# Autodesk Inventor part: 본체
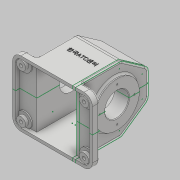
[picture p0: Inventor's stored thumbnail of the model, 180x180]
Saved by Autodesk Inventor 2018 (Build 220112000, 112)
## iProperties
Created: 2022-12
Part Number: 본체
Material: 일반
Document SubType Name: Modeling
Designer: home
Density: 1 g/cm^3
Appearance: 기본값
Author: home
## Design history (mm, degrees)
sketch "스케치1"
  geometry: L1 (53, -55)-(-53, -55); L2 (-67, -41)-(-67, 41); L3 (-53, 55)-(53, 55); L4 (67, 41)-(67, -41); L5 (67, -55)-(-67, 55); L6 (-67, -55)-(67, 55); A1 r 14 centre (53, -41) between (53, -55) and (67, -41); A2 r 14 centre (-53, -41) between (-67, -41) and (-53, -55); A3 r 14 centre (-53, 41) between (-53, 55) and (-67, 41); A4 r 14 centre (53, 41) between (67, 41) and (53, 55); 1 further point
  constraints: 12 end point, 8 point on circle, 8 point on line, 8 tangent, 4 centre point, 3 equal radius, 2 midpoint, 2 parallel, 1 horizontal, 1 perpendicular
  dimensions: "d0" = 134 distance of L5.end L6.end; "d1" = 110 distance of L6.start L5.end; "d2" = 14 radius of A1
extrude "돌출1" new body sketch "스케치1" distance "d3" = 12; taper "d4" = 0 deg
sketch "스케치2"
  geometry: L1 (67, 41)-(67, -41) reference; L2 (53, -55)-(-53, -55) reference; L3 (-67, -41)-(-67, 41) reference; L4 (-53, 55)-(53, 55) reference; C1 r 7.5 at (-53, 41); C2 r 7.5 at (53, 41); C3 r 7.5 at (-53, -41); C4 r 7.5 at (53, -41); A1 r 14 centre (53, 41) between (67, 41) and (53, 55) reference; A2 r 14 centre (53, -41) between (53, -55) and (67, -41) reference; A3 r 14 centre (-53, -41) between (-67, -41) and (-53, -55) reference; A4 r 14 centre (-53, 41) between (-53, 55) and (-67, 41) reference; 1 further point
  constraints: 4 centre point, 4 coincident
  dimensions: "d5" = 15 diameter of C1; "d6" = 15 diameter of C2; "d7" = 15 diameter of C3; "d8" = 15 diameter of C4
extrude "돌출2" cut sketch "스케치2" distance "d9" = 2; taper "d10" = 0 deg
sketch "스케치3"
  geometry: L1 (120, 0)-(120, -82) reference; L2 (106, -96)-(0, -96) reference; L3 (-14, -82)-(-14, 0) reference; L4 (0, 14)-(106, 14) reference; C1 r 7.5 at (0, -82) reference; C2 r 7.5 at (0, 0) reference; C3 r 7.5 at (106, 0) reference; C4 r 7.5 at (106, -82) reference; C5 r 2.75 at (0, 0); C6 r 2.75 at (106, 0); C7 r 2.75 at (0, -82); C8 r 2.75 at (106, -82); A1 r 14 centre (106, 0) between (120, 0) and (106, 14) reference; A2 r 14 centre (106, -82) between (106, -96) and (120, -82) reference; A3 r 14 centre (0, -82) between (-14, -82) and (0, -96) reference; A4 r 14 centre (0, 0) between (0, 14) and (-14, 0) reference; 1 further point
  constraints: 4 centre point, 4 coincident
  dimensions: "d11" = 5.5 diameter of C5; "d12" = 5.5 diameter of C6; "d13" = 5.5 diameter of C7; "d14" = 5.5 diameter of C8
extrude "돌출3" cut sketch "스케치3" extent not by distance; stored distance "d15" = 2; taper "d16" = 0 deg
sketch "스케치4"
  geometry: L1 (12, -55)-(0, -55) reference; L2 (0, -55)-(0, 55) reference; L3 (0, 55)-(12, 55) reference; L4 (12, 55)-(12, -55) reference; L5 (0, 55)-(77, 55); L6 (77, 55)-(122, 23.491); L7 (122, 0)-(122, 23.491); L8 (122, 0)-(122, -23.491); L9 (77, -55)-(122, -23.491); L10 (0, -55)-(77, -55); 1 further point
  constraints: 12 end point, 1 horizontal, 1 vertical
  dimensions: "d17" = 122 distance of point (0, 0) L7.start; "d18" = 77 distance of L2.end L5.end; "d19" = 35 deg angle of L6 L5
extrude "돌출4" join sketch "스케치4" stored distance "d20" = 77; taper "d21" = 0 deg
fillet "모깎기1" dims "d22" = 10
feature "쉘1" dims "d27" = 5
sketch "스케치8"
  geometry: L1 (-18.285, 122)-(18.285, 122) reference; L2 (26.477, 117.736)-(53.192, 79.583) reference; L3 (55, 73.847)-(55, 12) reference; L4 (55, 12)-(55, 0) reference; L5 (55, 0)-(50, 0) reference; L6 (50, 0)-(50, 7) reference; L7 (50, 7)-(-50, 7) reference; L8 (-50, 7)-(-50, 0) reference; L9 (-50, 0)-(-55, 0) reference; L10 (-55, 0)-(-55, 12) reference; L11 (-55, 12)-(-55, 73.847) reference; L12 (-53.192, 79.583)-(-26.477, 117.736) reference; L13 (-55, 12)-(55, 12) reference; A1 r 10 centre (-18.285, 112) between (-18.285, 122) and (-26.477, 117.736) reference; A2 r 10 centre (18.285, 112) between (26.477, 117.736) and (18.285, 122) reference; A3 r 10 centre (45, 73.847) between (55, 73.847) and (53.192, 79.583) reference; A4 r 10 centre (-45, 73.847) between (-53.192, 79.583) and (-55, 73.847) reference; 1 further point
  node "절단 모서리 투영5"
sketch "스케치9"
  geometry: 1 further point
sketch "스케치10"
  geometry: L1 (76.477, 110.736)-(103.192, 72.583) reference; L2 (105, 66.847)-(105, -7) reference; L3 (105, -7)-(100, -7) reference; L4 (100, -7)-(100, 0) reference; L5 (100, 0)-(100, 66.847) reference; L6 (99.096, 69.715)-(72.381, 107.868) reference; L7 (68.285, 110)-(31.715, 110) reference; L8 (27.619, 107.868)-(0.904, 69.715) reference; L9 (0, 66.847)-(0, 0) reference; L10 (100, 0)-(0, 0) reference; L11 (31.715, 115)-(68.285, 115) reference; L12 (-3.192, 72.583)-(23.523, 110.736) reference; L13 (-5, -7)-(-5, 66.847) reference; L14 (0, -7)-(-5, -7) reference; L15 (0, 0)-(0, -7) reference; A1 r 10 centre (68.285, 105) between (76.477, 110.736) and (68.285, 115) reference; A2 r 10 centre (95, 66.847) between (105, 66.847) and (103.192, 72.583) reference; A3 r 5 centre (95, 66.847) between (100, 66.847) and (99.096, 69.715) reference; A4 r 5 centre (68.285, 105) between (72.381, 107.868) and (68.285, 110) reference; A5 r 5 centre (31.715, 105) between (31.715, 110) and (27.619, 107.868) reference; A6 r 5 centre (5, 66.847) between (0.904, 69.715) and (0, 66.847) reference; A7 r 10 centre (31.715, 105) between (31.715, 115) and (23.523, 110.736) reference; A8 r 10 centre (5, 66.847) between (-3.192, 72.583) and (-5, 66.847) reference; 1 further point
  node "절단 모서리 투영6"
node "작업 평면1"
sketch "스케치12"
  geometry: 1 further point
sketch "스케치13"
  geometry: L1 (-18.285, 122)-(18.285, 122) reference; L2 (26.477, 117.736)-(53.192, 79.583) reference; L3 (55, 73.847)-(55, 12) reference; L4 (55, 12)-(55, 0) reference; L5 (55, 0)-(50, 0) reference; L6 (50, 0)-(50, 7) reference; L7 (50, 7)-(-50, 7) reference; L8 (-50, 7)-(-50, 0) reference; L9 (-50, 0)-(-55, 0) reference; L10 (-55, 0)-(-55, 12) reference; L11 (-55, 12)-(-55, 73.847) reference; L12 (-53.192, 79.583)-(-26.477, 117.736) reference; L13 (-55, 12)-(55, 12) reference; L14 (0, 0)-(0, 65); C1 r 37.5 at (0, 65); A1 r 10 centre (-18.285, 112) between (-18.285, 122) and (-26.477, 117.736) reference; A2 r 10 centre (18.285, 112) between (26.477, 117.736) and (18.285, 122) reference; A3 r 10 centre (45, 73.847) between (55, 73.847) and (53.192, 79.583) reference; A4 r 10 centre (-45, 73.847) between (-53.192, 79.583) and (-55, 73.847) reference
  constraints: 2 end point, 1 centre point, 1 coincident, 1 vertical
  dimensions: "d31" = 65 distance of L14.start L14.end; "d32" = 75 diameter of C1
extrude "돌출6" join sketch "스케치13" distance "d33" = 5; taper "d34" = 0 deg
sketch "스케치15"
  geometry: 1 further point
sketch "스케치16"
  geometry: L1 (26.477, 117.736)-(53.192, 79.583) reference; L2 (55, 73.847)-(55, 12) reference; L3 (55, 12)-(55, 0) reference; L4 (55, 0)-(50, 0) reference; L5 (50, 0)-(50, 7) reference; L6 (50, 7)-(-50, 7) reference; L7 (-50, 7)-(-50, 0) reference; L8 (-50, 0)-(-55, 0) reference; L9 (-55, 0)-(-55, 12) reference; L10 (-55, 12)-(-55, 73.847) reference; L11 (-53.192, 79.583)-(-26.477, 117.736) reference; L12 (-18.285, 122)-(18.285, 122) reference; L13 (-55, 12)-(55, 12) reference; L14 (0, 0)-(0, 65); C1 r 31 at (0, 65); A1 r 10 centre (18.285, 112) between (26.477, 117.736) and (18.285, 122) reference; A2 r 10 centre (45, 73.847) between (55, 73.847) and (53.192, 79.583) reference; A3 r 10 centre (-45, 73.847) between (-53.192, 79.583) and (-55, 73.847) reference; A4 r 10 centre (-18.285, 112) between (-18.285, 122) and (-26.477, 117.736) reference
  constraints: 2 end point, 1 centre point, 1 coincident, 1 vertical
  dimensions: "d39" = 65 distance of L14.start L14.end; "d40" = 62 diameter of C1
extrude "돌출8" join sketch "스케치16" distance "d41" = 10; taper "d42" = 0 deg
sketch "스케치17"
  geometry: 1 further point
sketch "스케치18"
  geometry: L1 (50, -7)-(50, 58); C1 r 37.5 at (50, 58)
  constraints: 2 end point, 1 centre point, 1 coincident, 1 vertical
  dimensions: "d43" = 65 distance of L1.start L1.end; "d45" = 75 diameter of C1
extrude "돌출9" join sketch "스케치18" distance "d46" = 14; taper "d47" = 0 deg
chamfer "모따기1" distance "d48" = 14; stored, may be unused: second distance "d49" = 2, angle "d50" = 45 deg
sketch "스케치19"
  geometry: 1 further point
hole "구멍1" diameter "d53" = 40; stored, may be unused: countersink angle "d57" = 90 deg, drill point angle "d59" = 0 deg; dims "d54" = 6.35, "d55" = 40, "d56" = 24, "d58" = 77, "d60" = 10, "d61" = 10
sketch "스케치20"
  geometry: L1 (38.5, 102.5)-(43.5, 102.5) reference; L2 (43.5, 102.5)-(43.5, 85) reference; L3 (43.5, 85)-(19.5, 85) reference; L4 (19.5, 85)-(19.5, 88.5) reference; L5 (19.5, 88.5)-(33.5, 102.5) reference; L6 (33.5, 102.5)-(33.5, 117) reference; L7 (33.5, 117)-(-33.5, 117) reference; L8 (-33.5, 117)-(-33.5, 85) reference; L9 (-33.5, 85)-(-48.5, 85) reference; L10 (-48.5, 85)-(-48.5, 96) reference; L11 (-48.5, 96)-(-38.5, 96) reference; L12 (-38.5, 96)-(-38.5, 122) reference; L13 (-38.5, 122)-(38.5, 122) reference; L14 (38.5, 122)-(38.5, 102.5) reference; L15 (-62, 7)-(-62, 0) reference; L16 (-62, 0)-(-67, 0) reference; L17 (-67, 0)-(-67, 12) reference; L18 (-67, 12)-(-38.5, 12) reference; L19 (-38.5, 12)-(-38.5, 34) reference; L20 (-38.5, 34)-(-48.5, 34) reference; L21 (-48.5, 34)-(-48.5, 45) reference; L22 (-48.5, 45)-(-33.5, 45) reference; L23 (-33.5, 45)-(-33.5, 7) reference; L24 (-33.5, 7)-(-62, 7) reference; L25 (67, 12)-(67, 0) reference; L26 (67, 0)-(62, 0) reference; L27 (62, 0)-(62, 7) reference; L28 (62, 7)-(33.5, 7) reference; L29 (33.5, 7)-(33.5, 27.5) reference; L30 (33.5, 27.5)-(19.5, 41.5) reference; L31 (19.5, 41.5)-(19.5, 45) reference; L32 (19.5, 45)-(43.5, 45) reference; L33 (43.5, 45)-(43.5, 27.5) reference; L34 (43.5, 27.5)-(38.5, 27.5) reference; L35 (38.5, 27.5)-(38.5, 12) reference; L36 (38.5, 12)-(67, 12) reference; L37 (38.5, 102.5)-(43.5, 102.5) reference; L38 (43.5, 102.5)-(43.5, 85) reference; L39 (43.5, 85)-(19.5, 85) reference; L40 (19.5, 85)-(19.5, 88.5) reference; L41 (19.5, 88.5)-(33.5, 102.5) reference; L42 (33.5, 102.5)-(33.5, 117) reference; L43 (33.5, 117)-(-33.5, 117) reference; L44 (-33.5, 117)-(-33.5, 85) reference; L45 (-33.5, 85)-(-48.5, 85) reference; L46 (-48.5, 85)-(-48.5, 96) reference; L47 (-48.5, 96)-(-38.5, 96) reference; L48 (-38.5, 96)-(-38.5, 122) reference; L49 (-38.5, 122)-(38.5, 122) reference; L50 (38.5, 122)-(38.5, 102.5) reference; L51 (-62, 7)-(-62, 0) reference; L52 (-62, 0)-(-67, 0) reference; L53 (-67, 0)-(-67, 12) reference; L54 (-67, 12)-(-38.5, 12) reference; L55 (-38.5, 12)-(-38.5, 34) reference; L56 (-38.5, 34)-(-48.5, 34) reference; L57 (-48.5, 34)-(-48.5, 45) reference; L58 (-48.5, 45)-(-33.5, 45) reference; L59 (-33.5, 45)-(-33.5, 7) reference; L60 (-33.5, 7)-(-62, 7) reference; L61 (67, 12)-(67, 0) reference; L62 (67, 0)-(62, 0) reference; L63 (62, 0)-(62, 7) reference; L64 (62, 7)-(33.5, 7) reference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; 1 further point
  node "절단 모서리 투영11"
  node "절단 모서리 투영12"
node "작업 평면2"
sketch "스케치21"
  geometry: C1 r 6 at (38.5, 18.285); 1 further point
  constraints: 1 centre point, 1 coincident
  dimensions: "d63" = 12 diameter of C1
extrude "돌출10" join sketch "스케치21" stored distance "d64" = 14; taper "d65" = 0 deg
fillet "모깎기2" dims "d66" = 3
hole "구멍2" diameter "d69" = 5.188; stored, may be unused: countersink angle "d73" = 90 deg, drill point angle "d75" = 0 deg; dims "d67" = 10, "d68" = 10, "d70" = 12, "d71" = 40, "d72" = 24, "d74" = 16
sketch "스케치22" dims "d77" = 52
  geometry: L1 (-35, -53)-(35, -53) reference; L2 (35, -53)-(35, -55) reference; L3 (35, -55)-(47, -55) reference; L4 (47, -55)-(47, -53) reference; L5 (47, -53)-(55, -53) reference; L6 (55, -53)-(55, -65) reference; L7 (55, -65)-(50, -65) reference; L8 (50, -65)-(50, -60) reference; L9 (50, -60)-(47.31, -60) reference; L10 (47.31, -60)-(47.31, -65) reference; L11 (47.31, -65)-(34.69, -65) reference; L12 (34.69, -65)-(34.69, -60) reference; L13 (34.69, -60)-(29.338, -60) reference; L14 (29.338, -60)-(29.338, -58) reference; L15 (29.338, -58)-(-29.338, -58) reference; L16 (-29.338, -58)-(-29.338, -60) reference; L17 (-29.338, -60)-(-34.69, -60) reference; L18 (-34.69, -60)-(-34.69, -65) reference; L19 (-34.69, -65)-(-47.31, -65) reference; L20 (-47.31, -65)-(-47.31, -60) reference; L21 (-47.31, -60)-(-50, -60) reference; L22 (-50, -60)-(-50, -65) reference; L23 (-50, -65)-(-55, -65) reference; L24 (-55, -65)-(-55, -53) reference; L25 (-55, -53)-(-47, -53) reference; L26 (-47, -53)-(-47, -55) reference; L27 (-47, -55)-(-35, -55) reference; L28 (-35, -55)-(-35, -53) reference; L29 (0, 0)-(0, 26); C1 r 20 at (0, 0) reference; C2 r 31 at (0, 0) reference; C3 r 20 at (0, 0) reference; 2 further points
  constraints: 2 end point, 1 coincident, 1 vertical, 1 vertical alignment, 2 other
hole "구멍3" sketch "스케치22" at (0, 26) diameter "d78" = 2.459; stored, may be unused: countersink angle "d82" = 90 deg, drill point angle "d84" = 118 deg; dims "d79" = 6, "d80" = 40, "d81" = 24, "d83" = 8.8
sketch "스케치23" dims "d88" = 58
  geometry: L1 (55, -53)-(55, -65) reference; L2 (55, -65)-(50, -65) reference; L3 (50, -65)-(50, -58) reference; L4 (50, -58)-(49.124, -58) reference; L5 (49.124, -58)-(49.124, -60) reference; L6 (49.124, -60)-(32.876, -60) reference; L7 (32.876, -60)-(32.876, -58) reference; L8 (32.876, -58)-(-32.876, -58) reference; L9 (-32.876, -58)-(-32.876, -60) reference; L10 (-32.876, -60)-(-49.124, -60) reference; L11 (-49.124, -60)-(-49.124, -58) reference; L12 (-49.124, -58)-(-50, -58) reference; L13 (-50, -58)-(-50, -65) reference; L14 (-50, -65)-(-55, -65) reference; L15 (-55, -65)-(-55, -53) reference; L16 (-55, -53)-(55, -53) reference; L17 (0, 0)-(0, 29); C1 r 20 at (0, 0) reference; C2 r 37.5 at (0, 0) reference; 1 further point
  constraints: 2 end point, 1 coincident, 1 vertical alignment, 2 other
hole "구멍4" sketch "스케치23" at (0, 29) diameter "d89" = 2.459; stored, may be unused: countersink angle "d93" = 90 deg, drill point angle "d95" = 118 deg; dims "d90" = 6, "d91" = 40, "d92" = 24, "d94" = 8.8
fillet "모깎기3" dims "d99" = 3
fillet "모깎기4" dims "d100" = 3
fillet "모깎기5" dims "d101" = 3
fillet "모깎기6" dims "d102" = 3
fillet "모깎기7" dims "d103" = 3
fillet "모깎기8" dims "d104" = 3
chamfer "모따기2" distance "d105" = 1; stored, may be unused: second distance "d106" = 2, angle "d107" = 45 deg
sketch "스케치24"
  geometry: L1 (17.5, 15)-(17.5, 73.847) reference; L2 (17.5, 73.847)-(88.5, 73.847) reference; L3 (88.5, 73.847)-(88.5, 15) reference; L4 (94.5, 9)-(106, 9) reference; L5 (106, 0)-(106, 9) reference; L6 (106, 0)-(0, 0) reference; L7 (0, 0)-(0, 9) reference; L8 (0, 9)-(11.5, 9) reference; L9 (-14.243, 0)-(14.257, 0); L10 (106, 0)-(0, 0) reference; L11 (14.257, 0)-(53.757, 0); L12 (53.757, 0)-(53.757, 50); A1 r 6 centre (94.5, 15) between (88.5, 15) and (94.5, 9) reference; A2 r 6 centre (11.5, 15) between (11.5, 9) and (17.5, 15) reference; 2 further points
  constraints: 6 end point, 2 point on line, 1 coincident, 1 perpendicular, 1 other
  dimensions: "d108" = 28.5 distance of L9.start L9.end; "d109" = 39.5 distance of L9.end L11.end; "d110" = 50 distance of L11.end L12.end
feature "엠보싱1" sketch "스케치24" dims "d111" = 0.5, "d112" = 0
sketch "스케치25"
  geometry: 1 further point
sketch "스케치26"
  geometry: 1 further point
sketch "스케치27"
  geometry: 1 further point
node "솔리드1"
pattern_circular "원형 패턴1" dims angle "d86" = 360 deg
pattern_circular "원형 패턴2" dims angle "d97" = 360 deg
node "절단 모서리 투영1"
node "절단 모서리 투영2"
node "절단 모서리 투영3"
node "절단 모서리 투영8"
node "절단 모서리 투영10"
node "절단 모서리 투영13"
node "절단 모서리 투영14"
node "절단 모서리 투영15"
other parameters: "d30" = 24, "d62" = 4
